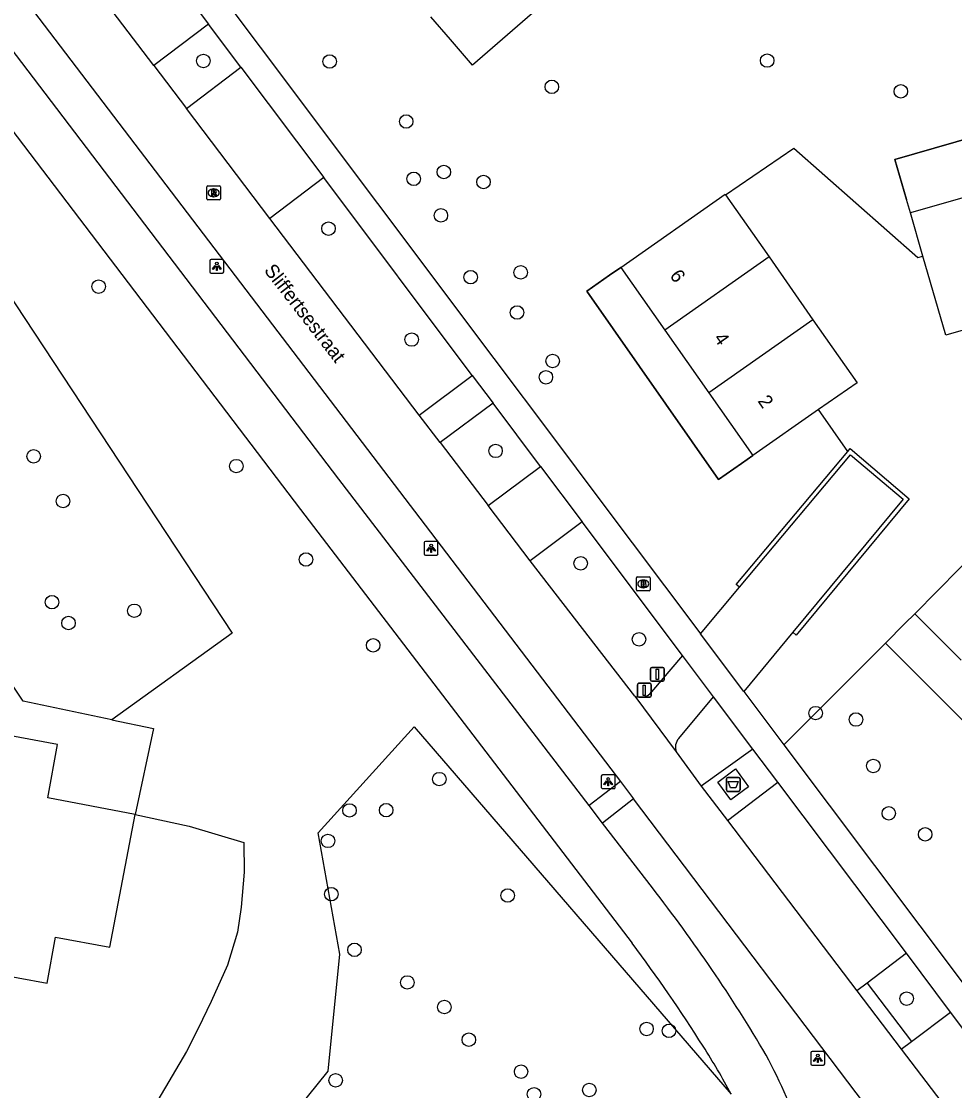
# Model space of a CAD drawing. Extents: x 156664 to 157568, y 383571 to 384421.
# Drawn here: x 156904.8 to 156972.4, y 384130.7 to 384208.1 of the extents above; entities that cross this region are included whole.
import ezdxf

# ---------------------------------------------------------------- set-up
doc = ezdxf.new("R2010")
doc.units = 0
for name, color, linetype in [('IMGEO_Afsluitpaal', 7, 'Continuous'), ('IMGEO_Afval_apart_plaats', 7, 'Continuous'), ('IMGEO_Berm_open', 7, 'Continuous'), ('IMGEO_Boom', 7, 'Continuous'), ('IMGEO_Brandkraan', 7, 'Continuous'), ('IMGEO_Erf', 7, 'Continuous'), ('IMGEO_Fietspad_gesloten', 7, 'Continuous'), ('IMGEO_Fietspad_open', 7, 'Continuous'), ('IMGEO_Groenvoorziening', 7, 'Continuous'), ('IMGEO_Lichtpunt', 7, 'Continuous'), ('IMGEO_Loofbos', 7, 'Continuous'), ('IMGEO_Muur', 7, 'Continuous'), ('IMGEO_Naaldbos', 7, 'Continuous'), ('IMGEO_Openbare_ruimte_label', 7, 'Continuous'), ('IMGEO_Pand', 7, 'Continuous'), ('IMGEO_Pand_nummerreeks', 7, 'Continuous'), ('IMGEO_Parkeervlak_open', 7, 'Continuous'), ('IMGEO_Rijbaan_lokaal_gesloten', 7, 'Continuous'), ('IMGEO_Rijbaan_lokaal_open', 7, 'Continuous'), ('IMGEO_Rioolput', 7, 'Continuous'), ('IMGEO_Voetpad_gesloten', 7, 'Continuous'), ('IMGEO_Voetpad_open', 7, 'Continuous')]:
    doc.layers.add(name, color=color, linetype=linetype)

msp = doc.modelspace()

# ---------------------------------------------------------------- linework, layer by layer
at = {"layer": 'IMGEO_Afsluitpaal'}
for p, q in [((156950.378, 384160.425), (156950.378, 384161.225)), ((156950.378, 384161.225), (156950.378, 384160.425)), ((156950.478, 384161.325), (156951.268, 384161.325)), ((156951.268, 384161.325), (156950.478, 384161.325)), ((156951.368, 384161.225), (156951.368, 384160.425)), ((156951.368, 384160.425), (156951.368, 384161.225)), ((156949.428, 384159.276), (156949.428, 384160.076)), ((156949.428, 384160.076), (156949.428, 384159.276)), ((156949.528, 384160.176), (156950.318, 384160.176)), ((156950.318, 384160.176), (156949.528, 384160.176)), ((156950.418, 384160.076), (156950.418, 384159.276)), ((156950.418, 384159.276), (156950.418, 384160.076)), ((156951.268, 384160.325), (156950.478, 384160.325)), ((156950.478, 384160.325), (156951.268, 384160.325)), ((156950.318, 384159.176), (156949.528, 384159.176)), ((156949.528, 384159.176), (156950.318, 384159.176))]:
    msp.add_line(p, q, dxfattribs=at)
for points in [[(156950.798, 384161.2), (156950.948, 384161.2), (156950.948, 384160.45), (156950.798, 384160.45), (156950.798, 384161.2)], [(156949.848, 384160.051), (156949.998, 384160.051), (156949.998, 384159.301), (156949.848, 384159.301), (156949.848, 384160.051)]]:
    msp.add_lwpolyline(points, dxfattribs=at)
for centre, start, end in [((156950.478, 384161.225), 90, 180), ((156950.478, 384161.225), 90, 180), ((156951.268, 384161.225), 0, 90), ((156951.268, 384161.225), 360, 90), ((156950.478, 384160.425), 180, 270), ((156950.478, 384160.425), 180, 270), ((156951.268, 384160.425), 270, 0), ((156951.268, 384160.425), 270, 0), ((156949.528, 384160.076), 90, 180), ((156949.528, 384160.076), 90, 180), ((156950.318, 384160.076), 0, 90), ((156950.318, 384160.076), 360, 90), ((156949.528, 384159.276), 180, 270), ((156949.528, 384159.276), 180, 270), ((156950.318, 384159.276), 270, 0), ((156950.318, 384159.276), 270, 0)]:
    msp.add_arc(centre, 0.1, start, end, dxfattribs=at)
at = {"layer": 'IMGEO_Afval_apart_plaats'}
for p, q in [((156955.87, 384152.455), (156955.87, 384153.255)), ((156955.87, 384153.255), (156955.87, 384152.455)), ((156955.97, 384153.355), (156956.76, 384153.355)), ((156956.76, 384153.355), (156955.97, 384153.355)), ((156956.86, 384153.255), (156956.86, 384152.455)), ((156956.86, 384152.455), (156956.86, 384153.255)), ((156956.76, 384152.355), (156955.97, 384152.355)), ((156955.97, 384152.355), (156956.76, 384152.355))]:
    msp.add_line(p, q, dxfattribs=at)
msp.add_lwpolyline([(156956.013, 384153.069), (156956.717, 384153.069), (156956.568, 384152.599), (156956.162, 384152.599), (156956.013, 384153.069)], dxfattribs=at)
for centre, start, end in [((156955.97, 384153.255), 90, 180), ((156955.97, 384153.255), 90, 180), ((156956.76, 384153.255), 0, 90), ((156956.76, 384153.255), 360, 90), ((156955.97, 384152.455), 180, 270), ((156955.97, 384152.455), 180, 270), ((156956.76, 384152.455), 270, 0), ((156956.76, 384152.455), 270, 0)]:
    msp.add_arc(centre, 0.1, start, end, dxfattribs=at)
at = {"layer": 'IMGEO_Berm_open'}
msp.add_lwpolyline([(156966.06, 384138.467), (156969.272, 384134.245)], dxfattribs=at)
at = {"layer": 'IMGEO_Boom'}
for centre in [(156917.988, 384205.227), (156927.137, 384205.187), (156958.823, 384205.253), (156943.231, 384203.351), (156968.508, 384203.025), (156932.682, 384200.841), (156935.408, 384197.187), (156933.225, 384196.695), (156938.277, 384196.465), (156935.194, 384194.045), (156927.052, 384193.089), (156937.352, 384189.576), (156940.974, 384189.92), (156910.399, 384188.893), (156940.71, 384187.014), (156933.08, 384185.058), (156943.289, 384183.506), (156942.799, 384182.327), (156939.154, 384176.999), (156905.693, 384176.603), (156920.375, 384175.898), (156907.826, 384173.368), (156925.421, 384169.139), (156945.323, 384168.861), (156907.022, 384166.05), (156912.986, 384165.427), (156908.22, 384164.535), (156949.547, 384163.361), (156930.289, 384162.926), (156962.338, 384158.019), (156965.255, 384157.552), (156966.515, 384154.196), (156935.074, 384153.242), (156928.573, 384150.974), (156931.227, 384150.992), (156967.635, 384150.763), (156970.271, 384149.242), (156927.015, 384148.769), (156927.256, 384144.91), (156940.03, 384144.813), (156928.933, 384140.884), (156932.757, 384138.524), (156935.445, 384136.739), (156968.927, 384137.355), (156950.091, 384135.159), (156937.217, 384134.378), (156951.715, 384135.019), (156941.002, 384132.065), (156927.57, 384131.437), (156945.945, 384130.737), (156941.942, 384130.43)]:
    msp.add_circle(centre, 0.489, dxfattribs=at)
at = {"layer": 'IMGEO_Brandkraan'}
for p, q in [((156949.35, 384166.948), (156949.35, 384167.8)), ((156949.425, 384167.874), (156950.277, 384167.874)), ((156949.838, 384167.654), (156949.863, 384167.654)), ((156950.351, 384167.8), (156950.351, 384166.948)), ((156950.277, 384166.874), (156949.425, 384166.874)), ((156949.861, 384167.094), (156949.836, 384167.094))]:
    msp.add_line(p, q, dxfattribs=at)
for points in [[(156949.35, 384166.948), (156949.35, 384167.8)], [(156949.425, 384167.874), (156950.277, 384167.874)], [(156949.698, 384167.574), (156949.698, 384167.174), (156949.911, 384167.174)], [(156949.929, 384167.574), (156949.698, 384167.574)], [(156949.877, 384167.493), (156949.823, 384167.493), (156949.823, 384167.417)], [(156949.823, 384167.417), (156949.876, 384167.417)], [(156950.351, 384167.8), (156950.351, 384166.948)], [(156950.277, 384166.874), (156949.425, 384166.874)], [(156949.885, 384167.341), (156949.823, 384167.341), (156949.823, 384167.26)], [(156949.823, 384167.26), (156949.885, 384167.26)]]:
    msp.add_lwpolyline(points, dxfattribs=at)
for centre, radius, start, end in [((156949.427, 384167.798), 0.0765, 91.55205, 178.44795), ((156949.427, 384167.798), 0.0765, 91.55205, 178.44795), ((156949.878, 384167.455), 0.0379, 267.82845, 90.93552), ((156949.933, 384167.429), 0.145, 59.4692, 91.53667), ((156949.958, 384167.476), 0.0922, 285.51372, 58.15012), ((156949.963, 384167.284), 0.105, 301.31148, 78.98903), ((156950.275, 384167.798), 0.0765, 1.55205, 88.44795), ((156950.275, 384167.798), 0.0765, 1.55205, 88.44795), ((156949.427, 384166.95), 0.0765, 181.55205, 268.44795), ((156949.427, 384166.95), 0.0765, 181.55205, 268.44795), ((156949.886, 384167.3), 0.0404, 269.87594, 90.50774), ((156949.917, 384167.425), 0.251, 268.66757, 293.53466), ((156950.275, 384166.95), 0.0765, 271.55205, 358.44795), ((156950.275, 384166.95), 0.0765, 271.55205, 358.44795)]:
    msp.add_arc(centre, radius, start, end, dxfattribs=at)
for centre, major_axis, ratio, start_param, end_param in [((156949.837, 384167.374), (-0.387, 0.002), 0.722429, 4.712389, 7.853982), ((156949.862, 384167.374), (-0.39, 0.002), 0.717154, 1.570796, 4.712389)]:
    msp.add_ellipse(centre, major_axis=major_axis, ratio=ratio, start_param=start_param, end_param=end_param, dxfattribs=at)
at = {"layer": 'IMGEO_Erf'}
msp.add_lwpolyline([(156967.386, 384163.072), (156968.807, 384164.496), (156969.513, 384165.203)], dxfattribs=at)
at = {"layer": 'IMGEO_Fietspad_gesloten'}
for points in [[(156849.254, 384272.327), (156925.032, 384172.754), (156949.045, 384141.371)], [(156945.927, 384151.336), (156927.81, 384174.952), (156867.867, 384253.653)], [(156946.909, 384150.056), (156945.927, 384151.336)], [(156950.51, 384145.361), (156946.909, 384150.056)]]:
    msp.add_lwpolyline(points, dxfattribs=at)
for centre, radius, start, end in [((156863.016, 384076.914), 111.087, 30.48417, 38.03635), ((156855.827, 384071.678), 116.39, 32.31787, 36.78313), ((156917.342, 384110.12), 43.854, 27.58281, 32.83983), ((156914.405, 384109.729), 50.202, 20.20282, 27.96194)]:
    msp.add_arc(centre, radius, start, end, dxfattribs=at)
at = {"layer": 'IMGEO_Fietspad_open'}
for points in [[(156948.198, 384153.058), (156945.927, 384151.336)], [(156949.137, 384151.82), (156946.909, 384150.056)]]:
    msp.add_lwpolyline(points, dxfattribs=at)
at = {"layer": 'IMGEO_Groenvoorziening'}
for points in [[(156969.2, 384194.233), (156968.921, 384195.187), (156968.071, 384198.098), (156984.074, 384202.696), (156984.917, 384199.793), (156985.199, 384198.821)], [(156955.81, 384195.537), (156960.769, 384198.905), (156969.731, 384190.994), (156970.105, 384191.102)], [(156957.791, 384176.663), (156956.957, 384176.083), (156955.31, 384174.937), (156945.765, 384188.562), (156947.412, 384189.712), (156948.233, 384190.285)], [(156964.672, 384176.966), (156962.55, 384179.984)], [(156967.386, 384163.072), (156960.044, 384155.717)], [(156981.295, 384153.461), (156980.584, 384152.741), (156979.171, 384151.311), (156967.386, 384163.072)], [(156911.353, 384157.536), (156914.369, 384156.907), (156913.042, 384150.679)], [(156913.042, 384150.679), (156916.959, 384149.844), (156920.928, 384148.664), (156920.951, 384146.515), (156920.715, 384143.965), (156920.467, 384142.161), (156919.737, 384139.785), (156918.56, 384137.15), (156917.618, 384135.197), (156916.768, 384133.516), (156911.324, 384124.31), (156910.294, 384122.041), (156909.558, 384119.746), (156909.426, 384118.952), (156909.382, 384117.878), (156909.514, 384116.775), (156909.839, 384114.445), (156910.897, 384109.877), (156911.053, 384109.423), (156911.232, 384109.029)]]:
    msp.add_lwpolyline(points, dxfattribs=at)
at = {"layer": 'IMGEO_Lichtpunt'}
for p, q in [((156918.463, 384190.765), (156918.463, 384189.958)), ((156918.463, 384190.765), (156918.463, 384189.958)), ((156919.365, 384190.86), (156918.557, 384190.86)), ((156919.365, 384190.86), (156918.557, 384190.86)), ((156919.459, 384189.958), (156919.459, 384190.765)), ((156919.459, 384189.958), (156919.459, 384190.765)), ((156918.557, 384189.864), (156919.365, 384189.864)), ((156918.557, 384189.864), (156919.365, 384189.864)), ((156933.987, 384170.357), (156933.987, 384169.55)), ((156933.987, 384170.357), (156933.987, 384169.55)), ((156934.889, 384170.452), (156934.081, 384170.452)), ((156934.889, 384170.452), (156934.081, 384170.452)), ((156934.983, 384169.55), (156934.983, 384170.357)), ((156934.983, 384169.55), (156934.983, 384170.357)), ((156934.081, 384169.456), (156934.889, 384169.456)), ((156934.081, 384169.456), (156934.889, 384169.456)), ((156946.814, 384153.451), (156946.814, 384152.644)), ((156946.814, 384153.451), (156946.814, 384152.644)), ((156947.716, 384153.546), (156946.908, 384153.546)), ((156947.716, 384153.546), (156946.908, 384153.546)), ((156947.81, 384152.644), (156947.81, 384153.451)), ((156947.81, 384152.644), (156947.81, 384153.451)), ((156946.908, 384152.55), (156947.716, 384152.55)), ((156946.908, 384152.55), (156947.716, 384152.55)), ((156961.996, 384133.432), (156961.996, 384132.625)), ((156961.996, 384133.432), (156961.996, 384132.625)), ((156962.898, 384133.527), (156962.09, 384133.527)), ((156962.898, 384133.527), (156962.09, 384133.527)), ((156962.992, 384132.625), (156962.992, 384133.432)), ((156962.992, 384132.625), (156962.992, 384133.432)), ((156962.09, 384132.531), (156962.898, 384132.531)), ((156962.09, 384132.531), (156962.898, 384132.531))]:
    msp.add_line(p, q, dxfattribs=at)
for points in [[(156918.837, 384190.429), (156918.876, 384190.401), (156918.688, 384190.139), (156918.65, 384190.166), (156918.837, 384190.429)], [(156918.939, 384190.381), (156918.986, 384190.381), (156918.986, 384190.059), (156918.939, 384190.059), (156918.939, 384190.381)], [(156919.049, 384190.401), (156919.087, 384190.428), (156919.274, 384190.166), (156919.235, 384190.138), (156919.049, 384190.401)], [(156934.361, 384170.021), (156934.4, 384169.993), (156934.212, 384169.731), (156934.174, 384169.758), (156934.361, 384170.021)], [(156934.463, 384169.973), (156934.51, 384169.973), (156934.51, 384169.651), (156934.463, 384169.651), (156934.463, 384169.973)], [(156934.573, 384169.993), (156934.611, 384170.02), (156934.798, 384169.758), (156934.759, 384169.73), (156934.573, 384169.993)], [(156947.188, 384153.115), (156947.227, 384153.087), (156947.039, 384152.825), (156947.001, 384152.852), (156947.188, 384153.115)], [(156947.29, 384153.067), (156947.337, 384153.067), (156947.337, 384152.745), (156947.29, 384152.745), (156947.29, 384153.067)], [(156947.4, 384153.087), (156947.438, 384153.114), (156947.625, 384152.852), (156947.586, 384152.824), (156947.4, 384153.087)], [(156962.37, 384133.096), (156962.409, 384133.068), (156962.221, 384132.806), (156962.183, 384132.833), (156962.37, 384133.096)], [(156962.472, 384133.048), (156962.519, 384133.048), (156962.519, 384132.726), (156962.472, 384132.726), (156962.472, 384133.048)], [(156962.582, 384133.068), (156962.62, 384133.095), (156962.807, 384132.833), (156962.768, 384132.805), (156962.582, 384133.068)]]:
    msp.add_lwpolyline(points, dxfattribs=at)
for centre in [(156918.962, 384190.563), (156934.486, 384170.155), (156947.313, 384153.249), (156962.495, 384133.23)]:
    msp.add_circle(centre, 0.0994, dxfattribs=at)
for centre, start, end in [((156918.557, 384190.765), 90, 180), ((156918.557, 384190.765), 90, 180), ((156919.365, 384190.765), 0, 90), ((156919.365, 384190.765), 0, 90), ((156918.557, 384189.958), 180, 270), ((156918.557, 384189.958), 180, 270), ((156919.365, 384189.958), 270, 0), ((156919.365, 384189.958), 270, 360), ((156934.081, 384170.357), 90, 180), ((156934.081, 384170.357), 90, 180), ((156934.889, 384170.357), 0, 90), ((156934.889, 384170.357), 0, 90), ((156934.081, 384169.55), 180, 270), ((156934.081, 384169.55), 180, 270), ((156934.889, 384169.55), 270, 0), ((156934.889, 384169.55), 270, 360), ((156946.908, 384153.451), 90, 180), ((156946.908, 384153.451), 90, 180), ((156947.716, 384153.451), 0, 90), ((156947.716, 384153.451), 0, 90), ((156946.908, 384152.644), 180, 270), ((156946.908, 384152.644), 180, 270), ((156947.716, 384152.644), 270, 0), ((156947.716, 384152.644), 270, 360), ((156962.09, 384133.432), 90, 180), ((156962.09, 384133.432), 90, 180), ((156962.898, 384133.432), 0, 90), ((156962.898, 384133.432), 0, 90), ((156962.09, 384132.625), 180, 270), ((156962.09, 384132.625), 180, 270), ((156962.898, 384132.625), 270, 0), ((156962.898, 384132.625), 270, 360)]:
    msp.add_arc(centre, 0.0946, start, end, dxfattribs=at)
at = {"layer": 'IMGEO_Loofbos'}
for points in [[(156896.18, 384200.013), (156920.073, 384163.8), (156911.353, 384157.536)], [(156911.353, 384157.536), (156904.931, 384158.876), (156892.709, 384177.194), (156886.083, 384181.928), (156885.768, 384185.506), (156881.456, 384187.505), (156889.009, 384196.195)]]:
    msp.add_lwpolyline(points, dxfattribs=at)
at = {"layer": 'IMGEO_Muur'}
for points in [[(156984.917, 384199.793), (156984.074, 384202.696), (156968.071, 384198.098), (156968.921, 384195.187)], [(156969.2, 384194.233), (156968.921, 384195.187)], [(156948.233, 384190.285), (156947.412, 384189.712)], [(156947.412, 384189.712), (156945.765, 384188.562), (156955.31, 384174.937), (156956.957, 384176.083)], [(156956.828, 384167.129), (156956.591, 384167.328), (156964.672, 384176.966)], [(156956.828, 384167.129), (156964.873, 384176.724), (156968.677, 384173.502), (156960.685, 384163.868)], [(156956.957, 384176.083), (156957.791, 384176.663)], [(156964.672, 384176.966), (156964.835, 384177.162), (156969.111, 384173.541), (156960.923, 384163.67), (156960.685, 384163.868)], [(156968.807, 384164.496), (156969.513, 384165.203)], [(156967.386, 384163.072), (156968.807, 384164.496)], [(156980.584, 384152.741), (156979.171, 384151.311), (156967.386, 384163.072)]]:
    msp.add_lwpolyline(points, dxfattribs=at)
at = {"layer": 'IMGEO_Naaldbos'}
msp.add_lwpolyline([(156942.127, 384113.492), (156930.191, 384114.906), (156914.869, 384116.99), (156927.02, 384132.097), (156927.884, 384140.558), (156926.305, 384149.362), (156933.269, 384157.022), (156956.212, 384130.426)], dxfattribs=at)
at = {"layer": 'IMGEO_Pand'}
for points in [[(156949.633, 384215.464), (156937.483, 384204.932), (156935.882, 384206.783), (156934.463, 384208.423)], [(156948.233, 384190.285), (156955.782, 384195.577), (156955.81, 384195.537)], [(156955.81, 384195.537), (156958.961, 384191.039)], [(156974.52, 384195.759), (156969.2, 384194.233)], [(156970.105, 384191.102), (156969.2, 384194.233)], [(156958.961, 384191.039), (156951.421, 384185.741)], [(156958.961, 384191.039), (156962.144, 384186.494)], [(156977.068, 384186.892), (156971.762, 384185.371), (156970.105, 384191.102)], [(156948.233, 384190.285), (156951.421, 384185.741)], [(156962.144, 384186.494), (156954.609, 384181.197)], [(156962.144, 384186.494), (156965.34, 384181.931), (156962.55, 384179.984)], [(156951.421, 384185.741), (156954.609, 384181.197)], [(156954.609, 384181.197), (156957.791, 384176.663)], [(156962.55, 384179.984), (156957.791, 384176.663)], [(156969.513, 384165.203), (156975.991, 384171.765), (156979.369, 384168.397)], [(156969.513, 384165.203), (156972.871, 384161.856)], [(156913.042, 384150.679), (156906.712, 384151.876), (156907.432, 384155.736), (156897.796, 384157.534), (156896.804, 384152.211), (156892.871, 384152.959), (156891.354, 384144.753), (156896.776, 384143.771), (156896.154, 384140.409), (156906.669, 384138.463), (156907.289, 384141.798), (156911.225, 384141.066), (156913.042, 384150.679)]]:
    msp.add_lwpolyline(points, dxfattribs=at)
at = {"layer": 'IMGEO_Parkeervlak_open'}
for points in [[(156918.348, 384207.896), (156914.397, 384204.906)], [(156916.761, 384201.782), (156920.708, 384204.77)], [(156926.719, 384196.787), (156922.806, 384193.826)], [(156933.628, 384179.594), (156937.458, 384182.455)], [(156938.971, 384180.443), (156935.139, 384177.608)], [(156938.611, 384173.044), (156942.416, 384175.861)], [(156945.427, 384171.858), (156941.651, 384169.047)], [(156968.907, 384140.631), (156966.06, 384138.467)], [(156966.06, 384138.467), (156965.332, 384137.913)], [(156969.272, 384134.245), (156972.116, 384136.364)], [(156968.544, 384133.691), (156969.272, 384134.245)]]:
    msp.add_lwpolyline(points, dxfattribs=at)
at = {"layer": 'IMGEO_Rijbaan_lokaal_gesloten'}
for points in [[(156869.636, 384256.091), (156947.883, 384153.474), (156948.198, 384153.058)], [(156914.397, 384204.906), (156905.044, 384217.212)], [(156914.397, 384204.906), (156916.761, 384201.782)], [(156922.806, 384193.826), (156916.761, 384201.782)], [(156933.628, 384179.594), (156922.806, 384193.826)], [(156935.139, 384177.608), (156933.628, 384179.594)], [(156935.139, 384177.608), (156938.611, 384173.044)], [(156941.651, 384169.047), (156938.611, 384173.044)], [(156949.248, 384159.24), (156941.651, 384169.047)], [(156949.248, 384159.24), (156952.237, 384155.208)], [(156952.237, 384155.208), (156954.053, 384152.742)], [(156948.198, 384153.058), (156949.137, 384151.82)], [(156954.053, 384152.742), (156955.947, 384150.252)], [(156967.768, 384127.243), (156949.137, 384151.82)], [(156955.947, 384150.252), (156965.332, 384137.913)], [(156965.332, 384137.913), (156968.544, 384133.691)], [(156968.544, 384133.691), (156976.126, 384123.722)]]:
    msp.add_lwpolyline(points, dxfattribs=at)
at = {"layer": 'IMGEO_Rijbaan_lokaal_open'}
for points in [[(156954.003, 384163.76), (156956.828, 384167.129)], [(156957.136, 384159.589), (156954.003, 384163.76)], [(156960.685, 384163.868), (156957.136, 384159.589)], [(156952.69, 384162.198), (156950.46, 384159.552)], [(156954.942, 384159.203), (156952.69, 384162.198)], [(156952.419, 384156.18), (156954.942, 384159.203)]]:
    msp.add_lwpolyline(points, dxfattribs=at)
for centre, radius, start, end in [((156949.643, 384160.215), 1.052, 247.92674, 320.94521), ((156953.136, 384155.543), 0.959, 138.35735, 200.43181)]:
    msp.add_arc(centre, radius, start, end, dxfattribs=at)
at = {"layer": 'IMGEO_Rioolput'}
for p, q in [((156918.234, 384195.255), (156918.234, 384196.107)), ((156918.309, 384196.181), (156919.161, 384196.181)), ((156919.235, 384196.107), (156919.235, 384195.255)), ((156918.745, 384195.401), (156918.72, 384195.401)), ((156918.722, 384195.961), (156918.747, 384195.961)), ((156919.161, 384195.181), (156918.309, 384195.181))]:
    msp.add_line(p, q, dxfattribs=at)
for points in [[(156918.234, 384195.255), (156918.234, 384196.107)], [(156918.309, 384196.181), (156919.161, 384196.181)], [(156919.235, 384196.107), (156919.235, 384195.255)], [(156918.823, 384195.879), (156918.571, 384195.881), (156918.571, 384195.481)], [(156918.571, 384195.481), (156918.695, 384195.481), (156918.695, 384195.643), (156918.706, 384195.643)], [(156918.749, 384195.8), (156918.695, 384195.8), (156918.695, 384195.719)], [(156918.695, 384195.719), (156918.747, 384195.719)], [(156918.753, 384195.614), (156918.824, 384195.481), (156918.964, 384195.481), (156918.899, 384195.607)], [(156919.161, 384195.181), (156918.309, 384195.181)]]:
    msp.add_lwpolyline(points, dxfattribs=at)
for centre, radius, start, end in [((156918.311, 384196.105), 0.0765, 91.55205, 178.44795), ((156918.311, 384196.105), 0.0765, 91.55205, 178.44795), ((156919.159, 384196.105), 0.0765, 1.55205, 88.44795), ((156919.159, 384196.105), 0.0765, 1.55205, 88.44795), ((156918.311, 384195.257), 0.0765, 181.55205, 268.44795), ((156918.311, 384195.257), 0.0765, 181.55205, 268.44795), ((156918.705, 384195.59), 0.0533, 26.02933, 88.69889), ((156918.731, 384195.908), 0.19, 274.7715, 282.96867), ((156918.755, 384195.704), 0.0964, 77.00612, 93.18647), ((156918.769, 384195.761), 0.0378, 276.66336, 79.67722), ((156918.822, 384195.769), 0.109, 350.36119, 89.41601), ((156918.82, 384195.769), 0.112, 277.58423, 350.98172), ((156918.804, 384195.554), 0.108, 29.51342, 73.79051), ((156919.159, 384195.257), 0.0765, 271.55205, 358.44795), ((156919.159, 384195.257), 0.0765, 271.55205, 358.44795)]:
    msp.add_arc(centre, radius, start, end, dxfattribs=at)
for centre, major_axis, ratio, start_param, end_param in [((156918.721, 384195.681), (-0.387, 0.002), 0.722429, 4.712389, 7.853982), ((156918.746, 384195.681), (-0.39, 0.002), 0.717154, 1.570796, 4.712389)]:
    msp.add_ellipse(centre, major_axis=major_axis, ratio=ratio, start_param=start_param, end_param=end_param, dxfattribs=at)
at = {"layer": 'IMGEO_Voetpad_gesloten'}
msp.add_lwpolyline([(156955.246, 384153.023), (156956.529, 384153.975), (156957.484, 384152.687), (156956.202, 384151.735), (156955.246, 384153.023)], dxfattribs=at)
at = {"layer": 'IMGEO_Voetpad_open'}
for points in [[(156879.806, 384262.53), (156939.02, 384183.696), (156943.34, 384177.955), (156946.64, 384173.562), (156953.814, 384164.012), (156954.003, 384163.76)], [(156909.04, 384220.251), (156918.348, 384207.896)], [(156920.708, 384204.77), (156918.348, 384207.896)], [(156920.708, 384204.77), (156926.719, 384196.787)], [(156937.458, 384182.455), (156926.719, 384196.787)], [(156937.458, 384182.455), (156938.971, 384180.443)], [(156942.416, 384175.861), (156938.971, 384180.443)], [(156942.416, 384175.861), (156945.427, 384171.858)], [(156952.69, 384162.198), (156945.427, 384171.858)], [(156957.791, 384155.414), (156954.942, 384159.203)], [(156957.136, 384159.589), (156960.044, 384155.717)], [(156957.791, 384155.414), (156954.053, 384152.742)], [(156959.593, 384153.019), (156957.791, 384155.414)], [(156960.044, 384155.717), (156983.009, 384125.143), (156990.473, 384115.206), (156994.084, 384110.528)], [(156955.947, 384150.252), (156959.593, 384153.019)], [(156968.907, 384140.631), (156959.593, 384153.019)], [(156972.116, 384136.364), (156968.907, 384140.631)], [(156979.61, 384126.397), (156972.116, 384136.364)]]:
    msp.add_lwpolyline(points, dxfattribs=at)

# ---------------------------------------------------------------- texts
at = {"layer": 'IMGEO_Openbare_ruimte_label'}
msp.add_text('Sliffertsestraat', height=1, rotation=307.80965, dxfattribs=at).set_placement((156922.339, 384190.051))
at = {"layer": 'IMGEO_Pand_nummerreeks'}
for s, p in [('6', (156951.729, 384189.69)), ('4', (156954.918, 384185.144)), ('2', (156958.104, 384180.603))]:
    msp.add_text(s, height=1, rotation=305.05514, dxfattribs=at).set_placement(p)

doc.saveas('drawing.dxf')
